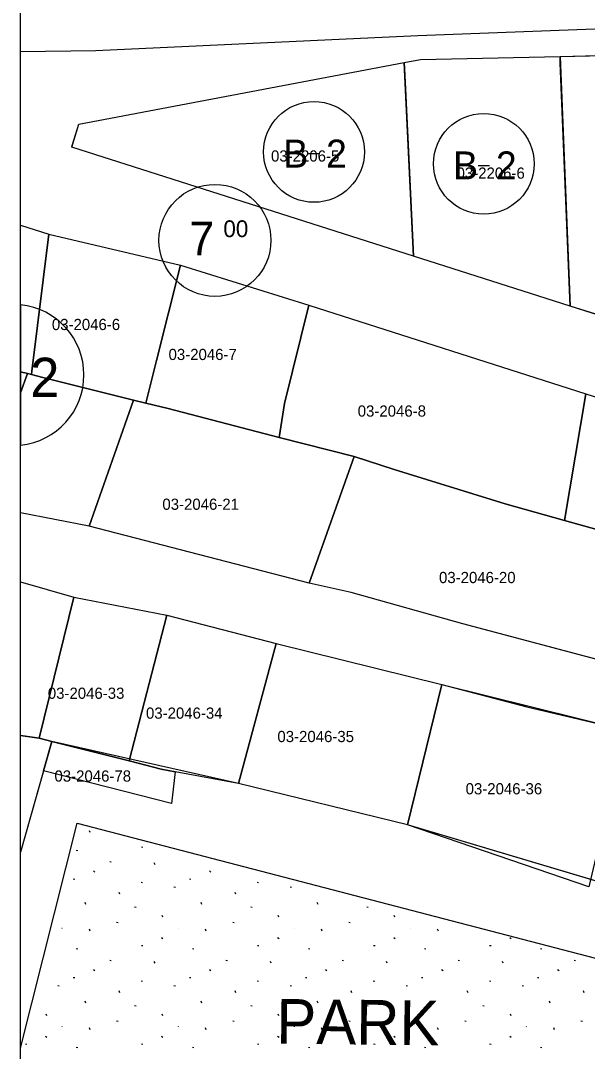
# Model space of a CAD drawing. Extents: x 413946 to 415528, y 4453939 to 4454944.
# Drawn here: x 413945.6 to 413996.2, y 4454565.5 to 4454657.6 of the extents above; entities that cross this region are included whole.
import ezdxf

# ---------------------------------------------------------------- set-up
doc = ezdxf.new("R2010")
doc.units = 0
for name, color, linetype in [('0_KADASTRO', 7, 'Continuous'), ('0_ÇERÇEVE', 7, 'Continuous'), ('Level 27', 7, 'Continuous'), ('Level 28', 7, 'Continuous'), ('Level 33', 7, 'Continuous'), ('Level 41', 7, 'Continuous'), ('Level 54', 7, 'Continuous'), ('Level 62', 7, 'Continuous'), ('SEMBOL', 7, 'Continuous'), ('SNR_FONKSIYON', 7, 'Continuous')]:
    doc.layers.add(name, color=color, linetype=linetype)

msp = doc.modelspace()

# ---------------------------------------------------------------- linework, layer by layer
at = {"layer": '0_KADASTRO'}
for points in [[(413979.836, 4454653.886), (413981.28, 4454654.16), (413993.748, 4454654.431), (413993.771, 4454653.864), (413994.644, 4454632.125), (413980.669, 4454636.586), (413979.955, 4454651.517)], [(413993.748, 4454654.431), (413997.592, 4454654.509), (414012.16, 4454654.83), (414016.135, 4454654.49), (414012.545, 4454626.411), (413994.644, 4454632.125), (413993.771, 4454653.864)], [(413950.132, 4454646.333), (413950.172, 4454646.464), (413950.756, 4454648.371), (413979.836, 4454653.886), (413979.955, 4454651.517), (413980.669, 4454636.586)], [(413946.54, 4454626), (413946.57, 4454626.3), (413948.1, 4454638.55), (413959.86, 4454635.79), (413957.7, 4454627.25), (413956.74, 4454623.46), (413955.66, 4454623.73), (413947.55, 4454625.75)], [(413956.74, 4454623.46), (413957.7, 4454627.25), (413959.86, 4454635.79), (413971.3, 4454632.2), (413969.14, 4454623.42), (413968.66, 4454620.39), (413958.75, 4454622.97)], [(413968.66, 4454620.39), (413969.14, 4454623.42), (413971.3, 4454632.2), (413996.06, 4454624.28), (413994.14, 4454612.97), (413988.85, 4454614.44), (413978.93, 4454617.52), (413975.36, 4454618.68)], [(413994.14, 4454612.97), (413996.06, 4454624.28), (414021.77, 4454616.06), (414020.28, 4454604.59), (414013.1, 4454606.89), (414003.23, 4454610.44)], [(413951.69, 4454612.46), (413955.66, 4454623.73), (413956.74, 4454623.46), (413958.75, 4454622.97), (413968.66, 4454620.39), (413975.36, 4454618.68), (413971.33, 4454607.37)], [(413971.33, 4454607.37), (413975.36, 4454618.68), (413978.93, 4454617.52), (413988.85, 4454614.44), (413994.14, 4454612.97), (414003.23, 4454610.44), (413999.85, 4454599.81), (413985.06, 4454603.72), (413975.09, 4454606.52)], [(413947.21, 4454593.52), (413950.31, 4454606.11), (413958.63, 4454604.51), (413955.27, 4454591.49), (413948.35, 4454593.23)], [(413955.27, 4454591.49), (413958.63, 4454604.51), (413968.4, 4454601.97), (413965.02, 4454589.46), (413959.365, 4454590.509), (413958.12, 4454590.74)], [(413965.02, 4454589.46), (413968.4, 4454601.97), (413983.19, 4454598.31), (413980.12, 4454585.77)], [(413980.12, 4454585.77), (413983.19, 4454598.31), (413990.78, 4454596.31), (413999.62, 4454594.22), (413996.32, 4454580.23)], [(413947.61, 4454590.61), (413948.35, 4454593.23), (413955.27, 4454591.49), (413958.12, 4454590.74), (413959.365, 4454590.509), (413959.04, 4454587.68)]]:
    msp.add_lwpolyline(points, close=True, dxfattribs=at)
for points in [[(413945.566, 4454639.351), (413948.1, 4454638.55), (413946.57, 4454626.3), (413946.54, 4454626), (413946.17, 4454626.09), (413945.566, 4454626.253)], [(413945.566, 4454626.253), (413945.566, 4454639.351)], [(413945.566, 4454624.36), (413945.566, 4454626.253)], [(413945.566, 4454626.253), (413946.17, 4454626.09), (413945.566, 4454624.36)], [(413945.566, 4454624.36), (413946.17, 4454626.09), (413946.54, 4454626), (413947.55, 4454625.75), (413955.66, 4454623.73), (413951.69, 4454612.46), (413945.566, 4454613.643)], [(413945.566, 4454613.643), (413945.566, 4454624.36)], [(413945.566, 4454593.745), (413945.566, 4454607.485)], [(413945.566, 4454607.485), (413950.31, 4454606.11), (413947.21, 4454593.52), (413945.566, 4454593.745)], [(413945.566, 4454583.334), (413945.566, 4454593.745)], [(413945.566, 4454593.745), (413947.21, 4454593.52), (413948.35, 4454593.23), (413947.61, 4454590.61), (413945.566, 4454583.334)]]:
    msp.add_lwpolyline(points, dxfattribs=at)
at = {"layer": '0_ÇERÇEVE'}
msp.add_lwpolyline([(413945.566, 4454943.957), (415494.137, 4454943.957), (415494.137, 4453939.478), (413945.566, 4453939.478)], close=True, dxfattribs=at)
at = {"layer": 'Level 27'}
for p, q in [((413981.28, 4454654.16), (413993.748, 4454654.431)), ((413993.748, 4454654.431), (414012.16, 4454654.83)), ((413950.756, 4454648.371), (413979.836, 4454653.886)), ((413979.836, 4454653.886), (413981.28, 4454654.16)), ((413950.132, 4454646.333), (413950.756, 4454648.371)), ((413980.669, 4454636.586), (413950.132, 4454646.333)), ((413945.566, 4454639.351), (413948.1, 4454638.55)), ((413948.1, 4454638.55), (413959.86, 4454635.79)), ((413994.644, 4454632.125), (413980.669, 4454636.586)), ((413959.86, 4454635.79), (413971.3, 4454632.2)), ((413971.3, 4454632.2), (413996.06, 4454624.28)), ((414012.545, 4454626.411), (413994.644, 4454632.125)), ((413996.06, 4454624.28), (414021.77, 4454616.06)), ((413951.69, 4454612.46), (413945.566, 4454613.643)), ((413971.33, 4454607.37), (413951.69, 4454612.46)), ((413945.566, 4454607.485), (413950.31, 4454606.11)), ((413975.09, 4454606.52), (413971.33, 4454607.37)), ((413950.31, 4454606.11), (413958.63, 4454604.51)), ((413985.06, 4454603.72), (413975.09, 4454606.52)), ((413958.63, 4454604.51), (413968.4, 4454601.97)), ((413999.85, 4454599.81), (413985.06, 4454603.72)), ((413968.4, 4454601.97), (413983.19, 4454598.31)), ((413983.19, 4454598.31), (413999.62, 4454594.22))]:
    msp.add_line(p, q, dxfattribs=at)
at = {"layer": 'Level 28'}
for p, q in [((413948.342, 4454593.232), (413945.566, 4454583.339)), ((413965.02, 4454589.46), (413948.342, 4454593.232)), ((413980.12, 4454585.77), (413965.02, 4454589.46)), ((413945.566, 4454565.837), (413950.63, 4454585.924)), ((413950.63, 4454585.924), (414012.06, 4454569.894)), ((414015.207, 4454575.324), (413980.12, 4454585.77))]:
    msp.add_line(p, q, dxfattribs=at)
at = {"layer": 'Level 41'}
for p, q in [((413951.778, 4454585.086), (413951.713, 4454585.249)), ((413951.778, 4454585.086), (413951.713, 4454585.249)), ((413950.538, 4454583.518), (413950.664, 4454583.495)), ((413950.538, 4454583.518), (413950.664, 4454583.495)), ((413956.358, 4454583.813), (413956.484, 4454583.788)), ((413956.358, 4454583.813), (413956.484, 4454583.788)), ((413953.538, 4454582.494), (413953.663, 4454582.47)), ((413953.538, 4454582.494), (413953.663, 4454582.47)), ((413957.571, 4454582.215), (413957.506, 4454582.377)), ((413957.571, 4454582.215), (413957.506, 4454582.377)), ((413950.268, 4454580.951), (413950.394, 4454580.927)), ((413950.268, 4454580.951), (413950.394, 4454580.927)), ((413952.063, 4454581.656), (413952.19, 4454581.557)), ((413952.063, 4454581.656), (413952.19, 4454581.557)), ((413960.636, 4454580.951), (413960.762, 4454580.927)), ((413960.636, 4454580.951), (413960.762, 4454580.927)), ((413962.431, 4454581.656), (413962.558, 4454581.557)), ((413962.431, 4454581.656), (413962.558, 4454581.557)), ((413956.331, 4454580.647), (413956.457, 4454580.623)), ((413956.331, 4454580.647), (413956.457, 4454580.623)), ((413959.26, 4454580.237), (413959.386, 4454580.212)), ((413959.26, 4454580.237), (413959.386, 4454580.212)), ((413966.699, 4454580.647), (413966.825, 4454580.623)), ((413966.699, 4454580.647), (413966.825, 4454580.623)), ((413969.628, 4454580.237), (413969.754, 4454580.212)), ((413969.628, 4454580.237), (413969.754, 4454580.212)), ((413954.428, 4454579.578), (413954.362, 4454579.74)), ((413954.428, 4454579.578), (413954.362, 4454579.74)), ((413964.796, 4454579.578), (413964.73, 4454579.74)), ((413964.796, 4454579.578), (413964.73, 4454579.74)), ((413951.397, 4454578.663), (413951.332, 4454578.826)), ((413951.397, 4454578.663), (413951.332, 4454578.826)), ((413955.747, 4454578.442), (413955.873, 4454578.419)), ((413955.747, 4454578.442), (413955.873, 4454578.419)), ((413961.765, 4454578.663), (413961.7, 4454578.826)), ((413961.765, 4454578.663), (413961.7, 4454578.826)), ((413966.115, 4454578.442), (413966.241, 4454578.419)), ((413966.115, 4454578.442), (413966.241, 4454578.419)), ((413972.133, 4454578.663), (413972.068, 4454578.826)), ((413972.133, 4454578.663), (413972.068, 4454578.826)), ((413976.483, 4454578.442), (413976.609, 4454578.419)), ((413976.483, 4454578.442), (413976.609, 4454578.419)), ((413954.143, 4454577.075), (413954.269, 4454577.05)), ((413954.143, 4454577.075), (413954.269, 4454577.05)), ((413958.269, 4454577.514), (413958.205, 4454577.675)), ((413958.269, 4454577.514), (413958.205, 4454577.675)), ((413964.511, 4454577.075), (413964.637, 4454577.05)), ((413964.511, 4454577.075), (413964.637, 4454577.05)), ((413968.637, 4454577.514), (413968.573, 4454577.675)), ((413968.637, 4454577.514), (413968.573, 4454577.675)), ((413974.879, 4454577.075), (413975.005, 4454577.05)), ((413974.879, 4454577.075), (413975.005, 4454577.05)), ((413979.005, 4454577.514), (413978.941, 4454577.675)), ((413979.005, 4454577.514), (413978.941, 4454577.675)), ((413949.259, 4454576.55), (413949.267, 4454576.548)), ((413949.259, 4454576.55), (413949.267, 4454576.548)), ((413951.778, 4454576.28), (413951.713, 4454576.443)), ((413951.778, 4454576.28), (413951.713, 4454576.443)), ((413959.627, 4454576.55), (413959.635, 4454576.548)), ((413959.627, 4454576.55), (413959.635, 4454576.548)), ((413962.146, 4454576.28), (413962.081, 4454576.443)), ((413962.146, 4454576.28), (413962.081, 4454576.443)), ((413969.995, 4454576.55), (413970.003, 4454576.548)), ((413969.995, 4454576.55), (413970.003, 4454576.548)), ((413972.514, 4454576.28), (413972.449, 4454576.443)), ((413972.514, 4454576.28), (413972.449, 4454576.443)), ((413980.363, 4454576.55), (413980.371, 4454576.548)), ((413980.363, 4454576.55), (413980.371, 4454576.548)), ((413982.882, 4454576.28), (413982.817, 4454576.443)), ((413982.882, 4454576.28), (413982.817, 4454576.443)), ((413958.152, 4454575.711), (413958.279, 4454575.613)), ((413958.152, 4454575.711), (413958.279, 4454575.613)), ((413968.52, 4454575.711), (413968.647, 4454575.613)), ((413968.52, 4454575.711), (413968.647, 4454575.613)), ((413978.888, 4454575.711), (413979.015, 4454575.613)), ((413978.888, 4454575.711), (413979.015, 4454575.613)), ((413989.256, 4454575.711), (413989.383, 4454575.613)), ((413989.256, 4454575.711), (413989.383, 4454575.613)), ((413950.538, 4454574.712), (413950.664, 4454574.689)), ((413950.538, 4454574.712), (413950.664, 4454574.689)), ((413956.358, 4454575.007), (413956.484, 4454574.982)), ((413956.358, 4454575.007), (413956.484, 4454574.982)), ((413960.906, 4454574.712), (413961.032, 4454574.689)), ((413960.906, 4454574.712), (413961.032, 4454574.689)), ((413966.726, 4454575.007), (413966.852, 4454574.982)), ((413966.726, 4454575.007), (413966.852, 4454574.982)), ((413971.274, 4454574.712), (413971.4, 4454574.689)), ((413971.274, 4454574.712), (413971.4, 4454574.689)), ((413977.094, 4454575.007), (413977.22, 4454574.982)), ((413977.094, 4454575.007), (413977.22, 4454574.982)), ((413981.642, 4454574.712), (413981.768, 4454574.689)), ((413981.642, 4454574.712), (413981.768, 4454574.689)), ((413987.462, 4454575.007), (413987.588, 4454574.982)), ((413987.462, 4454575.007), (413987.588, 4454574.982)), ((413992.01, 4454574.712), (413992.136, 4454574.689)), ((413992.01, 4454574.712), (413992.136, 4454574.689)), ((413953.538, 4454573.688), (413953.663, 4454573.664)), ((413953.538, 4454573.688), (413953.663, 4454573.664)), ((413957.571, 4454573.409), (413957.506, 4454573.571)), ((413957.571, 4454573.409), (413957.506, 4454573.571)), ((413963.906, 4454573.688), (413964.031, 4454573.664)), ((413963.906, 4454573.688), (413964.031, 4454573.664)), ((413967.939, 4454573.409), (413967.874, 4454573.571)), ((413967.939, 4454573.409), (413967.874, 4454573.571)), ((413974.274, 4454573.688), (413974.399, 4454573.664)), ((413974.274, 4454573.688), (413974.399, 4454573.664)), ((413978.307, 4454573.409), (413978.242, 4454573.571)), ((413978.307, 4454573.409), (413978.242, 4454573.571)), ((413984.642, 4454573.688), (413984.767, 4454573.664)), ((413984.642, 4454573.688), (413984.767, 4454573.664)), ((413988.675, 4454573.409), (413988.61, 4454573.571)), ((413988.675, 4454573.409), (413988.61, 4454573.571)), ((413995.01, 4454573.688), (413995.135, 4454573.664)), ((413995.01, 4454573.688), (413995.135, 4454573.664)), ((413952.063, 4454572.85), (413952.19, 4454572.751)), ((413952.063, 4454572.85), (413952.19, 4454572.751)), ((413962.431, 4454572.85), (413962.558, 4454572.751)), ((413962.431, 4454572.85), (413962.558, 4454572.751)), ((413972.799, 4454572.85), (413972.926, 4454572.751)), ((413972.799, 4454572.85), (413972.926, 4454572.751)), ((413983.167, 4454572.85), (413983.294, 4454572.751)), ((413983.167, 4454572.85), (413983.294, 4454572.751)), ((413993.535, 4454572.85), (413993.662, 4454572.751)), ((413993.535, 4454572.85), (413993.662, 4454572.751)), ((413950.268, 4454572.145), (413950.394, 4454572.121)), ((413950.268, 4454572.145), (413950.394, 4454572.121)), ((413956.331, 4454571.841), (413956.457, 4454571.817)), ((413956.331, 4454571.841), (413956.457, 4454571.817)), ((413960.636, 4454572.145), (413960.762, 4454572.121)), ((413960.636, 4454572.145), (413960.762, 4454572.121)), ((413966.699, 4454571.841), (413966.825, 4454571.817)), ((413966.699, 4454571.841), (413966.825, 4454571.817)), ((413971.004, 4454572.145), (413971.13, 4454572.121)), ((413971.004, 4454572.145), (413971.13, 4454572.121)), ((413977.067, 4454571.841), (413977.193, 4454571.817)), ((413977.067, 4454571.841), (413977.193, 4454571.817)), ((413981.372, 4454572.145), (413981.498, 4454572.121)), ((413981.372, 4454572.145), (413981.498, 4454572.121)), ((413987.435, 4454571.841), (413987.561, 4454571.817)), ((413987.435, 4454571.841), (413987.561, 4454571.817)), ((413991.74, 4454572.145), (413991.866, 4454572.121)), ((413991.74, 4454572.145), (413991.866, 4454572.121)), ((413948.892, 4454571.431), (413949.018, 4454571.406)), ((413948.892, 4454571.431), (413949.018, 4454571.406)), ((413954.428, 4454570.772), (413954.362, 4454570.934)), ((413954.428, 4454570.772), (413954.362, 4454570.934)), ((413959.26, 4454571.431), (413959.386, 4454571.406)), ((413959.26, 4454571.431), (413959.386, 4454571.406)), ((413964.796, 4454570.772), (413964.73, 4454570.934)), ((413964.796, 4454570.772), (413964.73, 4454570.934)), ((413969.628, 4454571.431), (413969.754, 4454571.406)), ((413969.628, 4454571.431), (413969.754, 4454571.406)), ((413975.164, 4454570.772), (413975.098, 4454570.934)), ((413975.164, 4454570.772), (413975.098, 4454570.934)), ((413979.996, 4454571.431), (413980.122, 4454571.406)), ((413979.996, 4454571.431), (413980.122, 4454571.406)), ((413985.532, 4454570.772), (413985.466, 4454570.934)), ((413985.532, 4454570.772), (413985.466, 4454570.934)), ((413990.364, 4454571.431), (413990.49, 4454571.406)), ((413990.364, 4454571.431), (413990.49, 4454571.406)), ((413995.9, 4454570.772), (413995.834, 4454570.934)), ((413995.9, 4454570.772), (413995.834, 4454570.934)), ((413951.397, 4454569.857), (413951.332, 4454570.02)), ((413951.397, 4454569.857), (413951.332, 4454570.02)), ((413961.765, 4454569.857), (413961.7, 4454570.02)), ((413961.765, 4454569.857), (413961.7, 4454570.02)), ((413972.133, 4454569.857), (413972.068, 4454570.02)), ((413972.133, 4454569.857), (413972.068, 4454570.02)), ((413982.501, 4454569.857), (413982.436, 4454570.02)), ((413982.501, 4454569.857), (413982.436, 4454570.02)), ((413992.869, 4454569.857), (413992.804, 4454570.02)), ((413992.869, 4454569.857), (413992.804, 4454570.02)), ((413947.901, 4454568.708), (413947.837, 4454568.869)), ((413947.901, 4454568.708), (413947.837, 4454568.869)), ((413955.747, 4454569.636), (413955.873, 4454569.613)), ((413955.747, 4454569.636), (413955.873, 4454569.613)), ((413958.269, 4454568.708), (413958.205, 4454568.869)), ((413958.269, 4454568.708), (413958.205, 4454568.869)), ((413966.115, 4454569.636), (413966.241, 4454569.613)), ((413966.115, 4454569.636), (413966.241, 4454569.613)), ((413968.637, 4454568.708), (413968.573, 4454568.869)), ((413968.637, 4454568.708), (413968.573, 4454568.869)), ((413976.483, 4454569.636), (413976.609, 4454569.613)), ((413976.483, 4454569.636), (413976.609, 4454569.613)), ((413979.005, 4454568.708), (413978.941, 4454568.869)), ((413979.005, 4454568.708), (413978.941, 4454568.869)), ((413986.851, 4454569.636), (413986.977, 4454569.613)), ((413986.851, 4454569.636), (413986.977, 4454569.613)), ((413989.373, 4454568.708), (413989.309, 4454568.869)), ((413989.373, 4454568.708), (413989.309, 4454568.869)), ((413954.143, 4454568.269), (413954.269, 4454568.244)), ((413954.143, 4454568.269), (413954.269, 4454568.244)), ((413964.511, 4454568.269), (413964.637, 4454568.244)), ((413964.511, 4454568.269), (413964.637, 4454568.244)), ((413974.879, 4454568.269), (413975.005, 4454568.244)), ((413974.879, 4454568.269), (413975.005, 4454568.244)), ((413985.247, 4454568.269), (413985.373, 4454568.244)), ((413985.247, 4454568.269), (413985.373, 4454568.244)), ((413995.615, 4454568.269), (413995.741, 4454568.244)), ((413995.615, 4454568.269), (413995.741, 4454568.244)), ((413949.259, 4454567.744), (413949.267, 4454567.742)), ((413949.259, 4454567.744), (413949.267, 4454567.742)), ((413951.778, 4454567.474), (413951.713, 4454567.637)), ((413951.778, 4454567.474), (413951.713, 4454567.637)), ((413959.627, 4454567.744), (413959.635, 4454567.742)), ((413959.627, 4454567.744), (413959.635, 4454567.742)), ((413962.146, 4454567.474), (413962.081, 4454567.637)), ((413962.146, 4454567.474), (413962.081, 4454567.637)), ((413969.995, 4454567.744), (413970.003, 4454567.742)), ((413969.995, 4454567.744), (413970.003, 4454567.742)), ((413972.514, 4454567.474), (413972.449, 4454567.637)), ((413972.514, 4454567.474), (413972.449, 4454567.637)), ((413980.363, 4454567.744), (413980.371, 4454567.742)), ((413980.363, 4454567.744), (413980.371, 4454567.742)), ((413982.882, 4454567.474), (413982.817, 4454567.637)), ((413982.882, 4454567.474), (413982.817, 4454567.637)), ((413990.731, 4454567.744), (413990.739, 4454567.742)), ((413990.731, 4454567.744), (413990.739, 4454567.742)), ((413993.25, 4454567.474), (413993.185, 4454567.637)), ((413993.25, 4454567.474), (413993.185, 4454567.637)), ((413945.99, 4454566.201), (413946.116, 4454566.176)), ((413945.99, 4454566.201), (413946.116, 4454566.176)), ((413947.784, 4454566.905), (413947.911, 4454566.807)), ((413947.784, 4454566.905), (413947.911, 4454566.807)), ((413956.358, 4454566.201), (413956.484, 4454566.176)), ((413956.358, 4454566.201), (413956.484, 4454566.176)), ((413958.152, 4454566.905), (413958.279, 4454566.807)), ((413958.152, 4454566.905), (413958.279, 4454566.807)), ((413966.726, 4454566.201), (413966.852, 4454566.176)), ((413966.726, 4454566.201), (413966.852, 4454566.176)), ((413968.52, 4454566.905), (413968.647, 4454566.807)), ((413968.52, 4454566.905), (413968.647, 4454566.807)), ((413977.094, 4454566.201), (413977.22, 4454566.176)), ((413977.094, 4454566.201), (413977.22, 4454566.176)), ((413978.888, 4454566.905), (413979.015, 4454566.807)), ((413978.888, 4454566.905), (413979.015, 4454566.807)), ((413987.462, 4454566.201), (413987.588, 4454566.176)), ((413987.462, 4454566.201), (413987.588, 4454566.176)), ((413989.256, 4454566.905), (413989.383, 4454566.807)), ((413989.256, 4454566.905), (413989.383, 4454566.807)), ((413950.538, 4454565.906), (413950.664, 4454565.883)), ((413950.538, 4454565.906), (413950.664, 4454565.883)), ((413960.906, 4454565.906), (413961.032, 4454565.883)), ((413960.906, 4454565.906), (413961.032, 4454565.883)), ((413971.274, 4454565.906), (413971.4, 4454565.883)), ((413971.274, 4454565.906), (413971.4, 4454565.883)), ((413981.642, 4454565.906), (413981.768, 4454565.883)), ((413981.642, 4454565.906), (413981.768, 4454565.883)), ((413992.01, 4454565.906), (413992.136, 4454565.883)), ((413992.01, 4454565.906), (413992.136, 4454565.883))]:
    msp.add_line(p, q, dxfattribs=at)
at = {"layer": 'Level 54'}
for points in [[(413994.644, 4454632.125), (413980.669, 4454636.586), (413979.836, 4454653.886), (413981.28, 4454654.16), (413993.748, 4454654.431)], [(413994.644, 4454632.125), (413993.748, 4454654.431), (414012.16, 4454654.83), (414017.252, 4454654.394), (414047.744, 4454651.79), (414047.49, 4454637.37), (414040.43, 4454617.51), (414019.944, 4454624.049), (414012.545, 4454626.411)], [(413980.669, 4454636.586), (413950.132, 4454646.333), (413950.756, 4454648.371), (413979.836, 4454653.886)]]:
    msp.add_lwpolyline(points, close=True, dxfattribs=at)
for points in [[(413945.566, 4454639.351), (413948.1, 4454638.55), (413959.86, 4454635.79), (413971.3, 4454632.2), (413996.06, 4454624.28), (414021.77, 4454616.06), (414037.29, 4454611.09), (414031, 4454601.54), (414026.04, 4454593.411), (414019.36, 4454595.13), (414009.65, 4454597.51), (414001.97, 4454599.44), (413999.85, 4454599.81), (413985.06, 4454603.72), (413975.09, 4454606.52), (413971.33, 4454607.37), (413951.69, 4454612.46), (413945.566, 4454613.643)], [(413945.566, 4454613.643), (413945.566, 4454639.351)], [(413945.566, 4454583.339), (413945.566, 4454607.485)], [(413945.566, 4454607.485), (413950.31, 4454606.11), (413958.63, 4454604.51), (413968.4, 4454601.97), (413983.19, 4454598.31), (413999.62, 4454594.22), (414007.83, 4454592.16), (414016.04, 4454589.99), (414022.515, 4454588.616), (414015.207, 4454575.324), (414015.207, 4454575.324), (413980.12, 4454585.77), (413965.02, 4454589.46), (413948.342, 4454593.232), (413945.566, 4454583.339)]]:
    msp.add_lwpolyline(points, dxfattribs=at)
at = {"layer": 'Level 62'}
for points in [[(413952.285, 4454654.945), (413981.045, 4454656.301), (414012.622, 4454657.499)], [(413945.566, 4454654.864), (413952.285, 4454654.945)]]:
    msp.add_lwpolyline(points, dxfattribs=at)
at = {"layer": 'SEMBOL'}
for p, q in [((413971.272, 4454645.744), (413972.272, 4454645.744)), ((413986.438, 4454644.686), (413987.438, 4454644.686)), ((413945.566, 4454625.759), (413945.62, 4454625.759))]:
    msp.add_line(p, q, dxfattribs=at)
msp.add_lwpolyline([(413945.566, 4454632.233), (413945.566, 4454619.7)], dxfattribs=at)
for centre, radius in [((413971.772, 4454645.893), 4.5), ((413986.938, 4454644.834), 4.5), ((413962.924, 4454637.991), 5)]:
    msp.add_circle(centre, radius, dxfattribs=at)
msp.add_arc((413944.92, 4454625.967), 6.3, 275.88722, 84.11278, dxfattribs=at)
at = {"layer": 'SNR_FONKSIYON'}
for points in [[(413994.644, 4454632.125), (413993.748, 4454654.431)], [(413979.836, 4454653.886), (413980.669, 4454636.586)]]:
    msp.add_lwpolyline(points, dxfattribs=at)

# ---------------------------------------------------------------- texts
at = {"layer": '0_KADASTRO'}
for s, p in [('03-2206-5', (413967.933, 4454645.032)), ('03-2206-6', (413984.504, 4454643.502)), ('03-2046-6', (413948.358, 4454629.978)), ('03-2046-7', (413958.78, 4454627.301)), ('03-2046-8', (413975.678, 4454622.245)), ('03-2046-21', (413958.228, 4454613.918)), ('03-2046-20', (413982.936, 4454607.372)), ('03-2046-33', (413947.996, 4454597.032)), ('03-2046-34', (413956.763, 4454595.256)), ('03-2046-35', (413968.503, 4454593.166)), ('03-2046-78', (413948.591, 4454589.636)), ('03-2046-36', (413985.314, 4454588.498))]:
    msp.add_text(s, height=1, dxfattribs=at).set_placement(p)
at = {"layer": 'Level 33'}
msp.add_text('PARK', height=4, rotation=359.4136, dxfattribs=at).set_placement((413968.391, 4454566.221))
at = {"layer": 'SEMBOL'}
for s, height, p in [('B', 2.5, (413969.026, 4454644.494)), ('2', 2.5, (413972.849, 4454644.494)), ('B', 2.5, (413984.192, 4454643.436)), ('2', 2.5, (413988.015, 4454643.436)), ('00', 1.5, (413963.674, 4454638.282)), ('7', 3, (413960.628, 4454636.651)), ('2', 3.5, (413946.428, 4454624.009))]:
    msp.add_text(s, height=height, dxfattribs=at).set_placement(p)

doc.saveas('drawing.dxf')
